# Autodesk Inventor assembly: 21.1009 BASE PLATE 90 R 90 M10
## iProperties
Created: 2009-01
Part Number: 21.1009 BASE PLATE 90 R 90 M10
Document SubType Name: Assembly
Designer: Administrator
Author: Administrator
